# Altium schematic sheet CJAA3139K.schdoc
size 127 x 101 mm
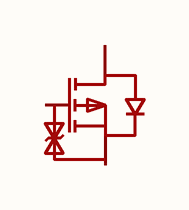
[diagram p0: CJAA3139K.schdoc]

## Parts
Q?  cjaa3139k  [WBFBP-03E_L1.0-W0.6-P0.64-BL]  (value not drawn)

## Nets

Not connected (* = marked no-connect by the designer): Q? 1(G) 2(S) 3(D)

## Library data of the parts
Q? = cjaa3139k: 数量:1个P沟道;漏源电压(Vdss):20V;连续漏极电流(Id):660mA;导通电阻(RDS(on)):520mΩ@4.5V;耗散功率(Pd):100mW;阈值电压(Vgs(th)):350mV;; Manufacturer: CJ(江苏长电/长晶); AddInBom: yes; ModelId: 072dcf228994456dbe83693440270b5f; ModelTransform: 40.1574,23.622,0,0,0,0,-0.001,0,0; Number: 1个P沟道; Drain to Source Voltage: 20V; Current - Continuous Drain(Id): 660mA; Pd - Power Dissipation: 100mW; Gate Threshold Voltage (Vgs(th)): 350mV; Input Capacitance(Ciss): 170pF; Reverse Transfer Capacitance (Crss@Vds): 15pF; Type: P沟道; Vgs: ±12V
